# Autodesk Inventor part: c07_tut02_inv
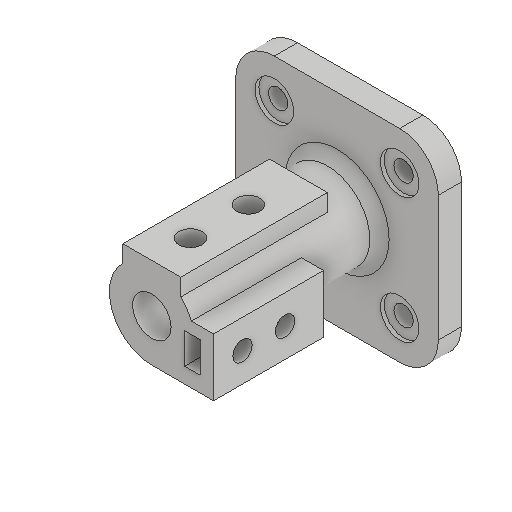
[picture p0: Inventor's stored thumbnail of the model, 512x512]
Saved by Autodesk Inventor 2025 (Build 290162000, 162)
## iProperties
Created: 2017-04
Part Number: c07_tut02_inv
Material: Generic
Document SubType Name: Modeling
Designer: CADCIM 00
Density: 1 g/cm^3
Appearance: Default
Author: CADCIM 00
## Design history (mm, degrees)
sketch "Sketch1"
  geometry: L1 (-32.5, -52.5)-(32.5, -52.5); L2 (52.5, -32.5)-(52.5, 32.5); L3 (32.5, 52.5)-(-32.5, 52.5); L4 (-52.5, 32.5)-(-52.5, -32.5); L5 (-52.5, -52.5)-(52.5, 52.5); L6 (52.5, -52.5)-(-52.5, 52.5); A1 r 20 centre (32.5, 32.5) between (52.5, 32.5) and (32.5, 52.5); A2 r 20 centre (-32.5, 32.5) between (-32.5, 52.5) and (-52.5, 32.5); A3 r 20 centre (-32.5, -32.5) between (-52.5, -32.5) and (-32.5, -52.5); A4 r 20 centre (32.5, -32.5) between (32.5, -52.5) and (52.5, -32.5); 1 further point
  constraints: 12 end point, 8 point on circle, 8 point on line, 8 tangent, 4 centre point, 3 equal radius, 2 midpoint, 2 parallel, 2 perpendicular, 1 horizontal
  dimensions: "d0" = 105 distance of L5.end L6.end; "d1" = 20 radius of A1
extrude "Extrusion1" new body sketch "Sketch1" distance "d2" = 12; taper "d3" = 0 deg
sketch "Sketch10"
  geometry: A1 r 20 centre (32.5, 32.5) between (52.5, 32.5) and (32.5, 52.5) reference; 1 further point
  constraints: 1 coincident
hole "Hole1" sketch "Sketch10" diameter "d6" = 10; stored, may be unused: countersink angle "d10" = 90 deg, drill point angle "d12" = 118 deg; dims "d7" = 6, "d8" = 20, "d9" = 2, "d11" = 8
hole "Hole2" diameter "d15" = 10; stored, may be unused: countersink angle "d19" = 90 deg, drill point angle "d21" = 118 deg; dims "d13" = 10, "d14" = 10, "d16" = 6, "d17" = 20, "d18" = 2, "d20" = 8
hole "Hole3" diameter "d24" = 10; stored, may be unused: countersink angle "d28" = 90 deg, drill point angle "d30" = 118 deg; dims "d22" = 10, "d23" = 10, "d25" = 6, "d26" = 20, "d27" = 2, "d29" = 8
hole "Hole4" diameter "d33" = 10; stored, may be unused: countersink angle "d37" = 90 deg, drill point angle "d39" = 118 deg; dims "d31" = 10, "d32" = 10, "d34" = 6, "d35" = 20, "d36" = 2, "d38" = 8
sketch "Sketch2"
  geometry: C1 r 22 at (0, 0); 1 further point
  constraints: 1 centre point, 1 coincident
  dimensions: "d40" = 44 diameter of C1
extrude "Extrusion2" join sketch "Sketch2" distance "d41" = 96; taper "d42" = 0 deg
sketch "Sketch3"
  geometry: L1 (-15, 25)-(15, 25); L2 (15, 25)-(15, 16.093); L3 (-15, 16.093)-(-15, 25); L4 (0, 0)-(0, 59.776); A1 r 22 centre (0, 0) between (-15, 16.093) and (15, 16.093) reference; 1 further point
  constraints: 8 end point, 2 point on circle, 1 horizontal, 1 parallel, 1 perpendicular, 1 vertical, 1 other
  dimensions: "d43" = 30 distance between parallel lines of L2 L3; "d44" = 25 distance from line of L1 point (0, 0)
extrude "Extrusion3" join sketch "Sketch3" distance "d45" = 76; taper "d46" = 0 deg
sketch "Sketch4"
  geometry: L1 (32, 8)-(20.494, 8); L2 (32, -22)-(32, 8); L3 (0, 0)-(52.5, 0); L4 (52.5, -32.5)-(52.5, 32.5) reference; L5 (0, -22)-(32, -22); A1 r 22 centre (0, 0) between (-15, 16.093) and (15, 16.093) reference; 1 further point
  constraints: 8 end point, 3 horizontal, 2 point on circle, 1 midpoint, 1 tangent, 1 vertical
  dimensions: "d47" = 30 distance of L2.start L1.start; "d48" = 32 distance from line of point (0, 0) L2
extrude "Extrusion4" join sketch "Sketch4" distance "d49" = 57; taper "d50" = 0 deg
sketch "Sketch6"
  geometry: L1 (25, 2)-(17, 2); L2 (17, 2)-(17, -14); L3 (17, -14)-(25, -14); L4 (25, -14)-(25, 2); L5 (0, 0)-(52.778, 0)
  constraints: 10 end point, 2 horizontal, 2 parallel, 1 perpendicular
  dimensions: "d51" = 8 distance of L1.start L1.end; "d52" = 16 distance of L3.end L1.start; "d53" = 25 distance from line of L4 L5.start; "d72" = 2 distance between parallel lines of L1 L5
extrude "Extrusion5" cut sketch "Sketch6" distance "d54" = 50; taper "d55" = 0 deg
sketch "Sketch7"
  geometry: C1 r 10 at (0, 0); 1 further point
  constraints: 1 centre point, 1 coincident
  dimensions: "d56" = 20 diameter of C1
extrude "Extrusion6" cut sketch "Sketch7" stored distance "d57" = 57; taper "d58" = 0 deg
sketch "Sketch8"
  geometry: L1 (30, 0)-(0, 0) reference; L2 (0, 0)-(0, 76) reference; C1 r 6 at (15, 50); C2 r 6 at (15, 20); 1 further point
  constraints: 2 centre point, 1 equal radius, 1 vertical alignment
  dimensions: "d59" = 30 distance of C2.centre C1.centre; "d60" = 12 diameter of C1; "d61" = 20 distance from line of L1 C2.centre; "d62" = 15 distance from line of L2 C2.centre
extrude "Extrusion7" cut sketch "Sketch8" stored distance "d63" = 57; taper "d64" = 0 deg
sketch "Sketch9"
  geometry: L1 (0, 0)-(0, 57) reference; L2 (30, 0)-(0, 0) reference; C1 r 5 at (15, 15); C2 r 5 at (15, 37); 1 further point
  constraints: 2 centre point, 1 equal radius, 1 vertical alignment
  dimensions: "d65" = 10 diameter of C1; "d66" = 22 distance of C2.centre C1.centre; "d67" = 15 distance from line of L1 C1.centre; "d68" = 15 distance from line of L2 C1.centre
extrude "Extrusion8" cut sketch "Sketch9" stored distance "d69" = 57; taper "d70" = 0 deg
fillet "Fillet1" dims "d71" = 5
body "Solid1"
